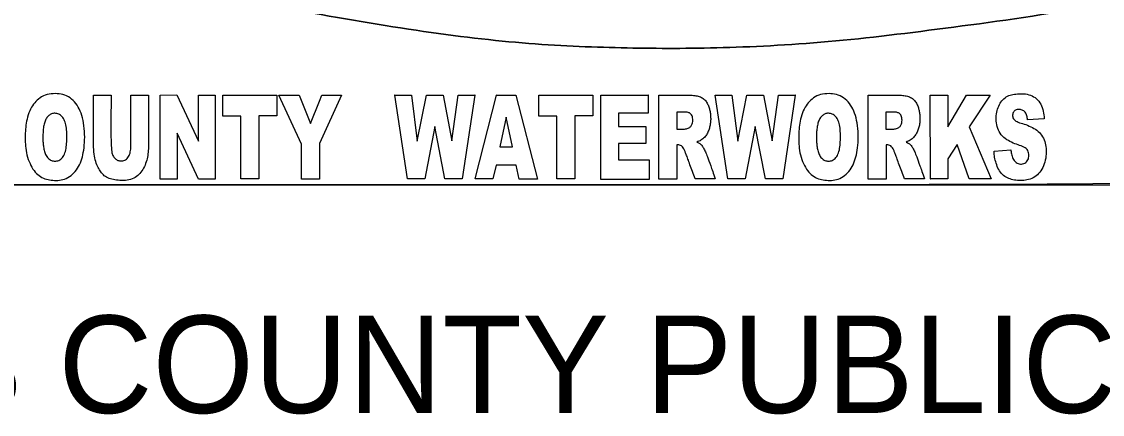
# Model space of a CAD drawing. Extents: x 837 to 1117, y 1316 to 1424.
# Drawn here: x 868.598 to 869.706, y 1400.982 to 1401.385 of the extents above; entities that cross this region are included whole.
import ezdxf

# ---------------------------------------------------------------- set-up
doc = ezdxf.new("R2010")
doc.units = 0
doc.layers.add('LLINES', color=7, linetype='Continuous')

# ---------------------------------------------------------------- blocks, each defined once
blk = doc.blocks.new('_U1')
at = {"layer": 'LLINES'}
for p, q in [((-0.506, -0.4637), (-0.506, -0.4637)), ((-0.4531, -0.466), (-0.4286, -0.466)), ((-0.4286, -0.466), (-0.4286, -0.466)), ((-0.4286, -0.466), (-0.4286, -0.466)), ((-0.4013, -0.466), (-0.4013, -0.4659)), ((-0.4013, -0.4659), (-0.3766, -0.4659)), ((0.3338, -0.583), (0.3338, -0.4659)), ((0.5709, -0.4637), (0.5709, -0.4637)), ((0.6251, -0.583), (0.6251, -0.4659)), ((-0.5069, -0.4912), (-0.5071, -0.4911)), ((0.3587, -0.4896), (0.3587, -0.5131)), ((0.57, -0.4912), (0.5697, -0.4911)), ((0.6499, -0.4896), (0.6499, -0.5131)), ((0.8702, -0.4987), (0.847, -0.5004)), ((0.3589, -0.5352), (0.3589, -0.583)), ((0.6502, -0.5352), (0.6502, -0.583)), ((0.8004, -0.5441), (0.8237, -0.5419)), ((0.3589, -0.583), (0.3338, -0.583)), ((0.4123, -0.5827), (0.3844, -0.5826)), ((0.6502, -0.583), (0.6251, -0.583)), ((0.7035, -0.5827), (0.6756, -0.5826)), ((-1.6222, -0.5907), (1.6237, -0.5907))]:
    blk.add_line(p, q, dxfattribs=at)
for points in [[(-0.3069, -0.583), (-0.337, -0.5188), (-0.337, -0.5828), (-0.3603, -0.5828), (-0.3603, -0.4658), (-0.3603, -0.4658), (-0.3603, -0.4658), (-0.3375, -0.4656), (-0.3072, -0.5302), (-0.3072, -0.466), (-0.284, -0.466), (-0.284, -0.583), (-0.3069, -0.583)], [(-0.2481, -0.5826), (-0.2481, -0.495), (-0.2731, -0.495), (-0.2731, -0.466), (-0.198, -0.4659), (-0.1981, -0.4947), (-0.2233, -0.4947), (-0.2233, -0.5826), (-0.2481, -0.5826)], [(-0.1637, -0.5831), (-0.1637, -0.5342), (-0.1952, -0.466), (-0.1671, -0.4659), (-0.1671, -0.466), (-0.1514, -0.5053), (-0.1388, -0.4741), (-0.1355, -0.466), (-0.108, -0.4659), (-0.108, -0.4658), (-0.108, -0.4659), (-0.108, -0.4659), (-0.1388, -0.5331), (-0.1388, -0.5338), (-0.1388, -0.5831), (-0.1637, -0.5831)], [(0.036, -0.5825), (0.022, -0.5096), (0.0079, -0.5825), (-0.0164, -0.5825), (-0.0339, -0.4659), (-0.0342, -0.4659), (-0.0339, -0.4658), (-0.0339, -0.4659), (-0.0107, -0.4659), (-0.0025, -0.5298), (0.0102, -0.4659), (0.0335, -0.4659), (0.0456, -0.5295), (0.0543, -0.4659), (0.0775, -0.4659), (0.0775, -0.4658), (0.078, -0.4659), (0.0775, -0.4659), (0.0601, -0.5825), (0.036, -0.5825)], [(0.1392, -0.583), (0.1352, -0.5634), (0.1072, -0.5634), (0.1028, -0.5827), (0.0779, -0.5827), (0.1079, -0.466), (0.108, -0.4656), (0.108, -0.466), (0.1347, -0.466), (0.1648, -0.583), (0.1392, -0.583)], [(0.1919, -0.5826), (0.1919, -0.495), (0.1668, -0.495), (0.1668, -0.466), (0.2419, -0.4659), (0.2419, -0.4947), (0.2166, -0.4947), (0.2166, -0.5826), (0.1919, -0.5826)], [(0.2528, -0.5832), (0.2528, -0.4659), (0.3189, -0.4659), (0.3191, -0.4659), (0.3189, -0.4659), (0.3189, -0.4908), (0.2777, -0.4908), (0.2777, -0.5095), (0.3158, -0.5095), (0.3158, -0.5334), (0.2775, -0.5334), (0.2775, -0.5561), (0.3201, -0.5561), (0.3201, -0.5832), (0.2528, -0.5832)], [(0.454, -0.5825), (0.4296, -0.5825), (0.4121, -0.4659), (0.4354, -0.4659), (0.4436, -0.5298), (0.4563, -0.4659), (0.4796, -0.4659), (0.4917, -0.5295), (0.5004, -0.4659), (0.5236, -0.4659), (0.5236, -0.4658), (0.5241, -0.4659), (0.5236, -0.4659), (0.5061, -0.5825), (0.482, -0.5825), (0.468, -0.5096), (0.454, -0.5825)], [(0.7963, -0.5827), (0.7963, -0.5826), (0.7658, -0.5826), (0.749, -0.5348), (0.736, -0.5544), (0.7361, -0.5826), (0.7119, -0.5826), (0.7114, -0.5826), (0.7119, -0.5826), (0.7115, -0.4658), (0.7361, -0.4658), (0.7361, -0.51), (0.7621, -0.4658), (0.7951, -0.4658), (0.7656, -0.5102), (0.7963, -0.5826), (0.7963, -0.5826), (0.7963, -0.5827)]]:
    blk.add_lwpolyline(points, dxfattribs=at)
blk.add_lwpolyline([(0.1123, -0.5381), (0.13, -0.5381), (0.121, -0.4966)], close=True, dxfattribs=at)
for points in [[(1.6237, -0.1737), (1.5983, -0.1738), (1.5491, -0.1739), (1.4571, -0.1888), (1.3294, -0.2187), (1.1518, -0.2794), (0.9561, -0.3425), (0.7506, -0.3705), (0.5779, -0.3926), (0.4178, -0.4012), (0.2906, -0.4008), (0.1563, -0.396), (0.0001, -0.3778), (-0.1826, -0.346), (-0.3534, -0.3102), (-0.4923, -0.2765), (-0.6042, -0.249), (-0.6984, -0.2398), (-0.7699, -0.2373), (-0.8303, -0.2385), (-0.9006, -0.2439), (-0.9843, -0.2576), (-1.0837, -0.2798), (-1.1773, -0.3031), (-1.27, -0.3237), (-1.3481, -0.3418), (-1.4221, -0.3516), (-1.497, -0.3622), (-1.5633, -0.3666), (-1.6073, -0.3674), (-1.6222, -0.3677), (-1.6222, -0.442), (-1.6222, -0.5164), (-1.6222, -0.5907), (-0.5402, -0.5907), (0.5418, -0.5907), (1.6237, -0.5907), (1.6237, -0.4517), (1.6237, -0.3127), (1.6237, -0.1737)], [(1.6237, -0.1737), (1.5983, -0.1738), (1.5491, -0.1739), (1.4571, -0.1888), (1.3294, -0.2187), (1.1518, -0.2794), (0.9561, -0.3425), (0.7506, -0.3705), (0.5779, -0.3926), (0.4178, -0.4012), (0.2906, -0.4008), (0.1563, -0.396), (0.0001, -0.3778), (-0.1826, -0.346), (-0.3534, -0.3102), (-0.4923, -0.2765), (-0.6042, -0.249), (-0.6984, -0.2398), (-0.7699, -0.2373), (-0.8303, -0.2385), (-0.9006, -0.2439), (-0.9843, -0.2576), (-1.0837, -0.2798), (-1.1773, -0.3031), (-1.27, -0.3237), (-1.3481, -0.3418), (-1.4221, -0.3516), (-1.497, -0.3622), (-1.5633, -0.3666), (-1.6073, -0.3674), (-1.6222, -0.3677)], [(-0.506, -0.4637), (-0.5031, -0.464), (-0.4957, -0.4646), (-0.4857, -0.469), (-0.4775, -0.4774), (-0.4715, -0.4875), (-0.4674, -0.5005), (-0.4655, -0.5164), (-0.4655, -0.5321), (-0.4673, -0.5462), (-0.4702, -0.5578), (-0.4751, -0.568), (-0.4823, -0.5765), (-0.4911, -0.5824), (-0.5005, -0.5848), (-0.5098, -0.5847), (-0.519, -0.5835), (-0.5272, -0.5798), (-0.5348, -0.5735), (-0.5404, -0.5644), (-0.5456, -0.5524), (-0.5478, -0.5397), (-0.5485, -0.5282), (-0.5484, -0.5189), (-0.5476, -0.508), (-0.5455, -0.4964), (-0.541, -0.4848), (-0.5354, -0.4761), (-0.5282, -0.4695), (-0.5182, -0.4644), (-0.5105, -0.4639), (-0.506, -0.4637)], [(-0.3766, -0.4659), (-0.3766, -0.4735), (-0.3766, -0.4937), (-0.3768, -0.5175), (-0.3764, -0.5362), (-0.3771, -0.5456), (-0.3784, -0.5543), (-0.3813, -0.5637), (-0.3857, -0.5715), (-0.3914, -0.5783), (-0.3991, -0.583), (-0.4089, -0.585), (-0.4191, -0.5846), (-0.4279, -0.5835), (-0.4356, -0.5805), (-0.441, -0.5759), (-0.4452, -0.57), (-0.4488, -0.5633), (-0.4515, -0.5538), (-0.4534, -0.5422), (-0.4532, -0.5281), (-0.4531, -0.5027), (-0.4531, -0.4818), (-0.4531, -0.466)], [(-0.4286, -0.466), (-0.429, -0.4898), (-0.4293, -0.515), (-0.4285, -0.5423), (-0.4275, -0.5475), (-0.425, -0.5525), (-0.4215, -0.556), (-0.4171, -0.5576), (-0.4124, -0.5576), (-0.4073, -0.5556), (-0.4033, -0.5504), (-0.4015, -0.5433), (-0.4011, -0.5351), (-0.4013, -0.528), (-0.4012, -0.5049), (-0.4013, -0.4847), (-0.4013, -0.466)], [(0.3338, -0.4659), (0.3422, -0.4659), (0.3551, -0.4659), (0.3698, -0.466), (0.3786, -0.4658), (0.3853, -0.4665), (0.3918, -0.468), (0.3967, -0.4713), (0.4004, -0.4757), (0.403, -0.4807), (0.4045, -0.4861), (0.4056, -0.4912), (0.4059, -0.4969), (0.4059, -0.5028), (0.4049, -0.5092), (0.4032, -0.5149), (0.4008, -0.5202), (0.3974, -0.5248), (0.3926, -0.5289), (0.3886, -0.5304), (0.3866, -0.5312)], [(0.5709, -0.4637), (0.5737, -0.464), (0.5811, -0.4646), (0.5912, -0.469), (0.5994, -0.4774), (0.6054, -0.4875), (0.6094, -0.5005), (0.6114, -0.5164), (0.6114, -0.5321), (0.6096, -0.5462), (0.6066, -0.5578), (0.6018, -0.568), (0.5946, -0.5765), (0.5858, -0.5824), (0.5763, -0.5848), (0.5671, -0.5847), (0.5579, -0.5835), (0.5497, -0.5798), (0.5421, -0.5735), (0.5365, -0.5644), (0.5312, -0.5524), (0.529, -0.5397), (0.5283, -0.5282), (0.5285, -0.5189), (0.5293, -0.508), (0.5314, -0.4964), (0.5358, -0.4848), (0.5414, -0.4761), (0.5487, -0.4695), (0.5586, -0.4644), (0.5664, -0.4639), (0.5709, -0.4637)], [(0.6251, -0.4659), (0.6334, -0.4659), (0.6464, -0.4659), (0.661, -0.466), (0.6699, -0.4658), (0.6765, -0.4665), (0.683, -0.468), (0.688, -0.4713), (0.6916, -0.4757), (0.6942, -0.4807), (0.6958, -0.4861), (0.6968, -0.4912), (0.6972, -0.4969), (0.6971, -0.5028), (0.6962, -0.5092), (0.6945, -0.5149), (0.692, -0.5202), (0.6886, -0.5248), (0.6838, -0.5289), (0.6798, -0.5304), (0.6778, -0.5312)], [(0.8237, -0.5419), (0.8238, -0.5434), (0.8244, -0.5479), (0.8262, -0.5544), (0.8308, -0.5601), (0.8369, -0.5625), (0.8434, -0.5611), (0.848, -0.5563), (0.8493, -0.5499), (0.848, -0.5429), (0.8423, -0.5377), (0.834, -0.5353), (0.8248, -0.5318), (0.8156, -0.5269), (0.8085, -0.5192), (0.8044, -0.5099), (0.8029, -0.4993), (0.8038, -0.4897), (0.8066, -0.4807), (0.811, -0.4736), (0.817, -0.468), (0.8245, -0.465), (0.8327, -0.464), (0.842, -0.4636), (0.8511, -0.4656), (0.8597, -0.4703), (0.8659, -0.4782), (0.8692, -0.4882), (0.8699, -0.4952), (0.8702, -0.4987)], [(-0.5071, -0.4911), (-0.5087, -0.4912), (-0.5117, -0.4914), (-0.5156, -0.4942), (-0.5191, -0.498), (-0.5212, -0.5033), (-0.5229, -0.5096), (-0.5236, -0.5167), (-0.5237, -0.5238), (-0.5237, -0.5304), (-0.5231, -0.5365), (-0.5221, -0.5427), (-0.5202, -0.5489), (-0.5167, -0.554), (-0.5119, -0.5573), (-0.5069, -0.5579), (-0.5016, -0.5573), (-0.4963, -0.5534), (-0.4928, -0.5467), (-0.4909, -0.538), (-0.4904, -0.5286), (-0.4902, -0.5186), (-0.4911, -0.5093), (-0.4932, -0.5015), (-0.4968, -0.4955), (-0.5016, -0.4918), (-0.5053, -0.4913), (-0.5069, -0.4912)], [(0.3587, -0.5131), (0.3602, -0.5131), (0.364, -0.5131), (0.3695, -0.5134), (0.3748, -0.5121), (0.3787, -0.5098), (0.3802, -0.506), (0.3811, -0.5026), (0.3811, -0.4992), (0.3804, -0.4962), (0.3795, -0.4935), (0.3773, -0.491), (0.3737, -0.4896), (0.3673, -0.4895), (0.3623, -0.4896), (0.3587, -0.4896)], [(0.5697, -0.4911), (0.5682, -0.4912), (0.5651, -0.4914), (0.5613, -0.4942), (0.5578, -0.498), (0.5556, -0.5033), (0.554, -0.5096), (0.5533, -0.5167), (0.5532, -0.5238), (0.5531, -0.5304), (0.5538, -0.5365), (0.5548, -0.5427), (0.5567, -0.5489), (0.5602, -0.554), (0.5649, -0.5573), (0.5699, -0.5579), (0.5752, -0.5573), (0.5806, -0.5534), (0.5841, -0.5467), (0.586, -0.538), (0.5865, -0.5286), (0.5866, -0.5186), (0.5858, -0.5093), (0.5837, -0.5015), (0.5801, -0.4955), (0.5753, -0.4918), (0.5716, -0.4913), (0.57, -0.4912)], [(0.6499, -0.5131), (0.6515, -0.5131), (0.6553, -0.5131), (0.6608, -0.5134), (0.666, -0.5121), (0.6699, -0.5098), (0.6714, -0.506), (0.6723, -0.5026), (0.6723, -0.4992), (0.6716, -0.4962), (0.6708, -0.4935), (0.6685, -0.491), (0.6649, -0.4896), (0.6585, -0.4895), (0.6535, -0.4896), (0.6499, -0.4896)], [(0.847, -0.5004), (0.8467, -0.4985), (0.8462, -0.4945), (0.844, -0.4893), (0.8395, -0.4864), (0.8347, -0.4853), (0.8299, -0.4864), (0.8268, -0.49), (0.8256, -0.4948), (0.8275, -0.5001), (0.8337, -0.5039), (0.8422, -0.5059), (0.8516, -0.5098), (0.8604, -0.5144), (0.867, -0.5215), (0.8712, -0.5302), (0.8733, -0.5398), (0.873, -0.551), (0.8706, -0.5619), (0.8657, -0.5716), (0.8591, -0.5787), (0.8508, -0.5833), (0.8416, -0.5849), (0.8328, -0.5849), (0.8245, -0.5835), (0.817, -0.5807), (0.8103, -0.5756), (0.8055, -0.5677), (0.8024, -0.5584), (0.8006, -0.5504), (0.8005, -0.5456), (0.8004, -0.5441)], [(0.3844, -0.5826), (0.383, -0.5789), (0.3806, -0.5724), (0.3768, -0.5625), (0.3743, -0.5546), (0.3717, -0.5484), (0.3702, -0.5442), (0.3687, -0.5406), (0.3667, -0.5376), (0.3641, -0.5356), (0.3613, -0.5352), (0.3596, -0.5352), (0.3589, -0.5352)], [(0.3866, -0.5312), (0.3875, -0.5316), (0.3897, -0.5326), (0.3931, -0.535), (0.3958, -0.5394), (0.3987, -0.5445), (0.4011, -0.551), (0.4057, -0.5638), (0.4095, -0.5745), (0.4123, -0.5827)], [(0.6756, -0.5826), (0.6742, -0.5789), (0.6718, -0.5724), (0.6681, -0.5625), (0.6655, -0.5546), (0.6629, -0.5484), (0.6615, -0.5442), (0.6599, -0.5406), (0.6579, -0.5376), (0.6553, -0.5356), (0.6525, -0.5352), (0.6508, -0.5352), (0.6502, -0.5352)], [(0.6778, -0.5312), (0.6788, -0.5316), (0.6809, -0.5326), (0.6844, -0.535), (0.6871, -0.5394), (0.69, -0.5445), (0.6924, -0.551), (0.6969, -0.5638), (0.7007, -0.5745), (0.7035, -0.5827)]]:
    blk.add_open_spline(points, degree=3, dxfattribs=at)

msp = doc.modelspace()

# ---------------------------------------------------------------- block references
at = {"xscale": 0.7363891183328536, "yscale": 0.7363891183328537}
msp.add_blockref('_U1', (869.0051, 1401.653), dxfattribs=at)

# ---------------------------------------------------------------- texts
at = {"layer": 'LLINES'}
msp.add_text('LOS ANGELES COUNTY PUBLIC WORKS', height=0.1, dxfattribs=at).set_placement((867.6616, 1400.9838))

doc.saveas('drawing.dxf')
